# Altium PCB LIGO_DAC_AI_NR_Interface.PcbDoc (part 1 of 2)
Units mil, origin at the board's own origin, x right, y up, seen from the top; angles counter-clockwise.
Board outline 2600 x 10000 mil, 4 copper layers (Top Layer, Mid-Layer 1, Mid-Layer 2, Bottom Layer), stack 61.8 mil thick; 21 components, 77 nets, 221 pads, 42 vias.
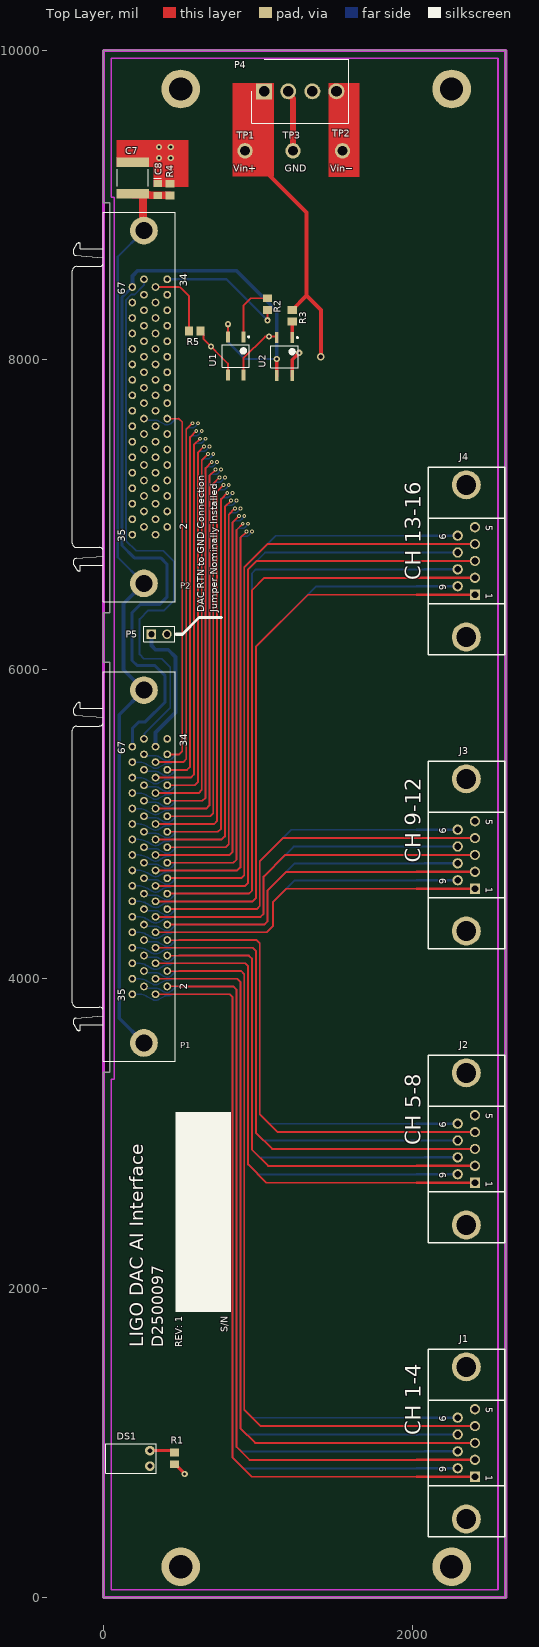
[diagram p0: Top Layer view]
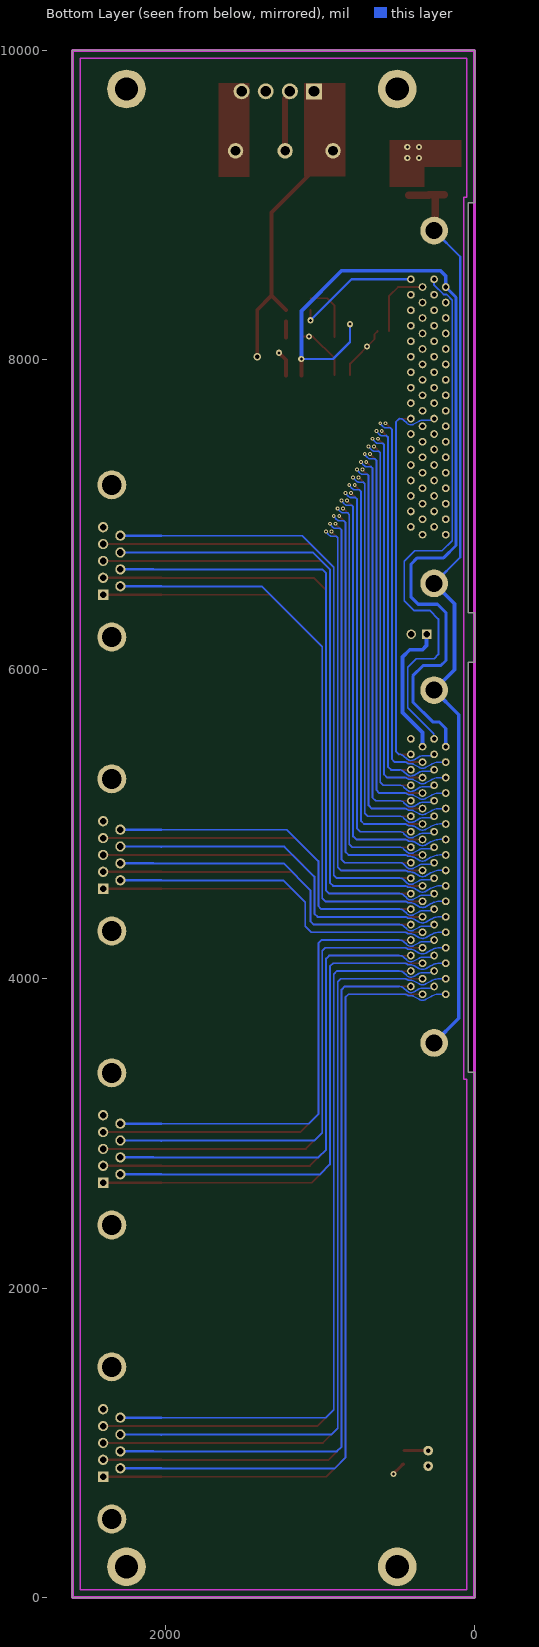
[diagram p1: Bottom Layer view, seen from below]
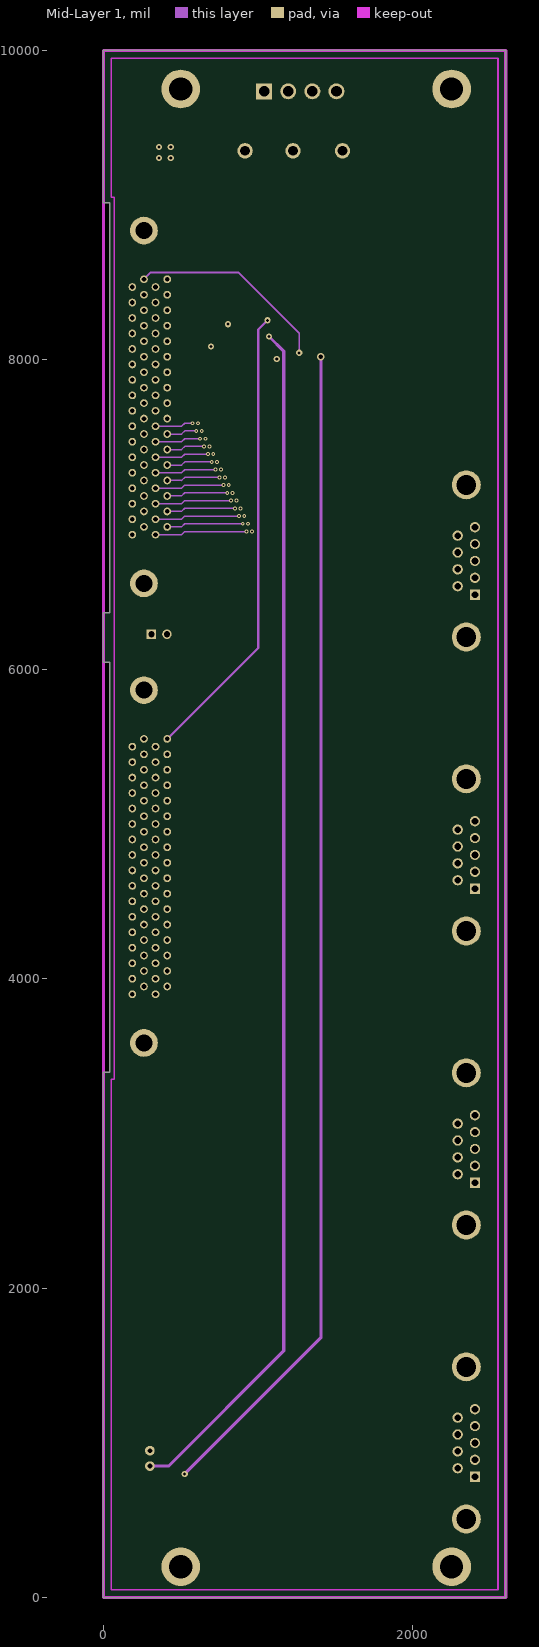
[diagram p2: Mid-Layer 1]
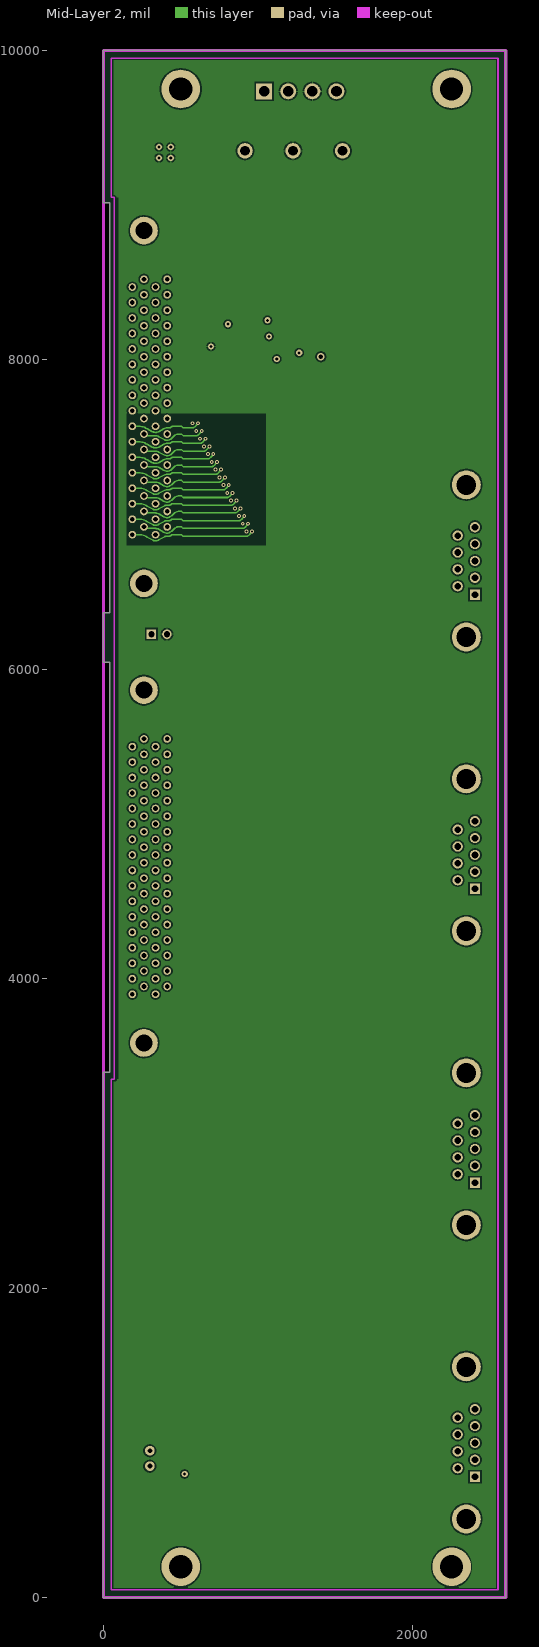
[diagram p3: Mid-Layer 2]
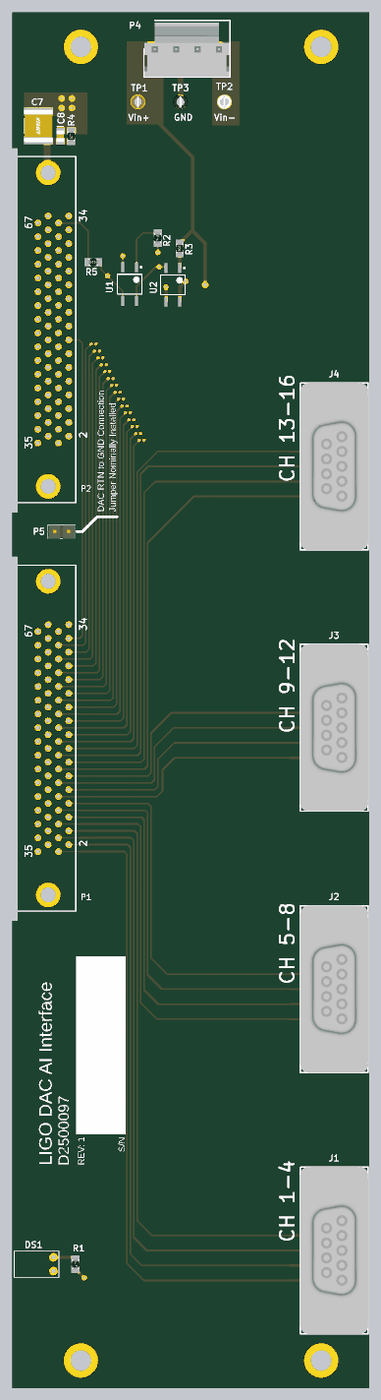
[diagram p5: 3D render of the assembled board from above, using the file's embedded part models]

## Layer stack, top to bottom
Top Solder: solder mask 0.4, Solder Resist, Dk 3.5
Top Layer: signal copper 1.4
Dielectric4: prepreg 8.6, FR-4, Dk 4.8
Mid-Layer 1: signal copper 1.4
Dielectric2: core 39, FR-4, Dk 4.8
Mid-Layer 2: signal copper 1.4
Dielectric3: prepreg 8.6, FR-4, Dk 4.8
Bottom Layer: signal copper 1.4
Bottom Solder: solder mask 0.4, Solder Resist, Dk 3.5

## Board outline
0,0 0,3395 40,3395 40,6045 0,6045 0,6365 40,6365 40,9015 0,9015 0,10000 2600,10000 2600,0

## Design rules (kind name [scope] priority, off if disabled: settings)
Clearance [All] p1: gap=10 ignorepadtopadclearanceinfootprint=FALSE
ComponentClearance ComponentClearance_1 [InComponent('P1')] p1: gap=0 collisioncheckmode=3 verticalgap=0 showdistances=FALSE
ComponentClearance ComponentClearance_2 [InComponent('P2')] p2: gap=0 collisioncheckmode=3 verticalgap=0 showdistances=FALSE
ComponentClearance ComponentClearance_3 [InComponent('DS1')] p3: gap=0 collisioncheckmode=3 verticalgap=0 showdistances=FALSE
ComponentClearance [All] p4: gap=10 collisioncheckmode=3 verticalgap=10 showdistances=FALSE
HoleSize [All] p1: absolutevalues=TRUE maxlimit=250 minlimit=12 maxpercent=80.000 minpercent=20.000
MinimumAnnularRing [All] p1: minimumring=6.5
PolygonConnect [All] p1: connectstyle=Relief reliefconductorwidth=10 reliefentries=4 polygonreliefangle="90 Angle" airgapwidth=10
RoutingVias [All] p1: holewidth=20 width=40 viastyle="Through Hole" minholewidth=12 minwidth=25 maxholewidth=28 maxwidth=50
SilkToSolderMaskClearance SilkscreenOverComponentPads [IsPad] p1: minsilkscreentomaskgap=5 clearancetoexposedcopper=TRUE
SolderMaskExpansion SolderMaskExpansion_1 [IsVia And (HoleDiameter = 12)] p1: expansion=5 istentingtop=FALSE
SolderMaskExpansion [All] p2: expansion=4 istentingtop=FALSE
SupplyNets "Schematic Supply Nets_4" [InNet('DGND')] p1: voltage=0.000
SupplyNets "Schematic Supply Nets_3" [InNet('Vin+')] p2: voltage=0.000
SupplyNets "Schematic Supply Nets_2" [InNet('GND')] p3: voltage=0.000
SupplyNets "Schematic Supply Nets_1" [InNet('Vin-')] p4: voltage=0.000
Width [All] p1: maxlimit=100 minlimit=8 preferedwidth=12
27 further rules are at their usual default settings.

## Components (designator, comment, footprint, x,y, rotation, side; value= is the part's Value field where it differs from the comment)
C7 "47u" CC5650-2220 190,9175 r270 top
C8 "100n" CC2013-0805 350,9100 r270 top
DS1 "LED" LED-1 300,900 r180 top
J1 "DB9F" DB9F-ST 2345,1000 r270 top locked
J2 "DB9F" DB9F-ST 2345,2900 r270 top locked
J3 "DB9F" DB9F-ST 2345,4800 r270 top
J4 "DB9F" DB9F-ST 2345,6700 r270 top locked
P1 "787082-7" 787082-7 0,4725 r90 top locked
P2 "787082-7" 787082-7 0,7695 r90 top locked
P4 "26-61-4040" HDRV4W155P0X396_1X4_1570X1001X1536P 1038.19,9735 r180 top
P5 "Header 2" TSW-102-XX-YY-S 310,6226.5 r0 top
R1 "2.21K" CR2012-0805 460,900 r270 top
R2 "499" CR2012-0805 1060,8360 r90 top
R3 "2.21K" CR2012-0805 1220,8285 r90 top
R4 "NL" CR2012-0805 430,9100 r90 top
R5 "NL" CR2012-0805 590,8185 r0 top
TP1 "Vin+" TP1-RED 915,9350 r0 top
TP2 "Vin−" TP1-WHT 1545,9350 r0 top
TP3 "GND" TP1-BLK 1225,9350 r0 top
U1 "PS2702-1-F3-A" PS2701A-1 855,8025 r270 top
U2 "PS2702-1-F3-A" PS2701A-1 1170,8020 r270 top

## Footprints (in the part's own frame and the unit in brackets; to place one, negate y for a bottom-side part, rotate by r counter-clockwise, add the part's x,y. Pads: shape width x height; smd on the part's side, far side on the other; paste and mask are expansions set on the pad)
787082-7 [mm] "Connector; D Subminiature 050 Series; 68 Position; Right Angle"
  round 1.27 hole 0.762: 1(-20.955,-8.555) 2(-19.685,-10.46) 3(-18.415,-8.555) 4(-17.145,-10.46) 5(-15.875,-8.555) 6(-14.605,-10.46) 7(-13.335,-8.555) 8(-12.065,-10.46) 9(-10.795,-8.555) 10(-9.525,-10.46) 11(-8.255,-8.555) 12(-6.985,-10.46) 13(-5.715,-8.555) 14(-4.445,-10.46) 15(-3.175,-8.555) 16(-1.905,-10.46) 17(-0.635,-8.555) 18(0.635,-10.46) 19(1.905,-8.555) 20(3.175,-10.46) 21(4.445,-8.555) 22(5.715,-10.46) 23(6.985,-8.555) 24(8.255,-10.46) 25(9.525,-8.555) 26(10.795,-10.46) 27(12.065,-8.555) 28(13.335,-10.46) 29(14.605,-8.555) 30(15.875,-10.46) 31(17.145,-8.555) 32(18.415,-10.46) 33(19.685,-8.555) 34(20.955,-10.46) 35(-20.955,-4.745) 36(-19.685,-6.65) 37(-18.415,-4.745) 38(-17.145,-6.65) 39(-15.875,-4.745) 40(-14.605,-6.65) 41(-13.335,-4.745) 42(-12.065,-6.65) 43(-10.795,-4.745) 44(-9.525,-6.65) 45(-8.255,-4.745) 46(-6.985,-6.65) 47(-5.715,-4.745) 48(-4.445,-6.65) 49(-3.175,-4.745) 50(-1.905,-6.65) 51(-0.635,-4.745) 52(0.635,-6.65) 53(1.905,-4.745) 54(3.175,-6.65) 55(4.445,-4.745) 56(5.715,-6.65) 57(6.985,-4.745) 58(8.255,-6.65) 59(9.525,-4.745) 60(10.795,-6.65) 61(12.065,-4.745) 62(13.335,-6.65) 63(14.605,-4.745) 64(15.875,-6.65) 65(17.145,-4.745) 66(18.415,-6.65) 67(19.685,-4.745) 68(20.955,-6.65)
  round 4.55 hole 2.77: 69(-28.955,-6.65) 70(28.955,-6.65)
  silkscreen extent -31.95,-11.76 31.95,5.11
CC2013-0805 [mm] "Chip Capacitor; Body 2.0 x 1.3 mm (LxW typ)"
  rect 1.15x1.4 smd: 1(-0.975,0) 2(0.975,0)
  silkscreen extent -1.85,-0.6 -1.85,0.6, body extent -1.1,-0.72 1.1,0.73, height 0.88
CC5650-2220 [mm] "Chip Capacitor, Body 5.6 x 5.0mm (LxW typ)"
  rect 1.6x5.3 smd: 1(-2.6,0) 2(2.6,0)
  silkscreen extent -1.4,-2.55 1.4,2.55, body extent -3.05,-2.7 3.05,2.7, height 1.8
CR2012-0805 [mm] "Chip Resistor; Body 2.0 x 1.3 mm (LxW typ)"
  rect 1.3x1.5 smd: 1(-0.95,0) 2(0.95,0)
  body extent -1,-0.62 1,0.63, height 0.46
DB9F-ST [mm] "Receptiacle; D Subminiature 9 Position; Straight"
  rect 1.69x1.69 hole 1.09: 1(5.54,1.42)
  round 1.69 hole 1.09: 2(2.77,1.42) 3(0,1.42) 4(-2.77,1.42) 5(-5.54,1.42) 6(4.155,-1.42) 7(1.385,-1.42) 8(-1.385,-1.42) 9(-4.155,-1.42)
  round 4.76 hole 3.26: 10(12.495,0) 11(-12.495,0)
  silkscreen extent -15.4,-6.27 15.4,6.27, body extent -15.44,-6.3 15.44,6.3, height 12.32
HDRV4W155P0X396_1X4_1570X1001X1536P [mm]
  rect 2.625x2.625 hole 1.75: 1(0,0)
  round 2.625 hole 1.75: 2(-3.96,0) 3(-7.92,0) 4(-11.88,0)
  silkscreen extent -13.91,-5.26 2.03,5.26, body extent -13.79,-4.83 1.91,5.17, height 14.73
LED-1 [mm] "Typical RED GaAs LED; 2 Leads"
  round 1.6 hole 0.8: 1(0,1.27) 2(0,-1.27)
  silkscreen extent -1.02,-2.41 7.24,2.41
PS2701A-1 [mm] "SOP, 4-Leads, Body 4.5x4.4mm (max), Pitch 2.54mm, IPC Medium Density"
  rect 1.8x0.6 smd: 1(-3.125,1.27) 2(-3.125,-1.27) 3(3.125,-1.27) 4(3.125,1.27)
  silkscreen extent -3.25,-2.25 1.83,2.25, body extent -2.2,-2.25 2.2,2.25, height 2.3
TP1-BLK [mm] "Testpoint pin, black"
  round 2.54 hole 1.58: 1(0,0)
  body extent -1.27,-1.27 1.27,1.27, height 4.89
TP1-RED [mm] "Testpoint pin, red"
  round 2.54 hole 1.58: 1(0,0)
  body extent -1.27,-1.27 1.27,1.27, height 4.89
TP1-WHT [mm] "Testpoint pin, white"
  round 2.54 hole 1.58: 1(0,0)
  body extent -1.27,-1.27 1.27,1.27, height 4.89
TSW-102-XX-YY-S [mm]
  rect 1.55x1.55 hole 1.02: 1(0,0)
  round 1.55 hole 1.02: 2(2.54,0)
  silkscreen extent -1.27,-1.27 3.81,1.27, body extent -1.39,-1.28 3.82,1.26, height 9.16

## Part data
C7: library part ChipCap, "Capacitor, surface mount", Part Number=445-C5750X7R1V476M230KCCT-ND, Tolerance=10%, Voltage Rating=35V
C8: library part ChipCap, "Capacitor, surface mount", Part Number=311-1140-1-ND, Tolerance=10%
DS1: "Panel mount LED", Part Number=67-1304-ND
J1 J2 J3 J4: "Receptacle Assembly, 9 Position, Right Angle, .318 Series", Part Number=A34072-ND
P1 P2: "Receptacle Assembly, Shielded, Right Angle, AMPLIMITE", Part Number=A31814-ND
P4: "Connector", Manufacturer_Name=Molex, Part Number=WM5226-ND
P5: "Header, 2-Pin", Part Number=SAM10844-ND
R1 R3: library part ChipRes1, "Resistor, surface mount", Part Number=311-2.21KCRCT-ND, Tolerance=1%
R2: library part ChipRes1, "Resistor, surface mount", Part Number=311-499CRCT-ND, Tolerance=1%
R4 R5: library part ChipRes1, "Resistor, surface mount", Tolerance=1%
TP1: library part TP_POSITIVE, "Testpoint, red", Part Number=5005K-ND
TP2: library part TP_NEGATIVE, "Testpoint, white", Part Number=5007K-ND
TP3: library part TP_GND, "Testpoint, black", Part Number=5006K-ND
U1 U2: library part PS2701A, "High Isolation Voltage SOP Photocoupler", Part Number=559-1027-1-ND

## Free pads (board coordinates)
  round 250 hole 150: 0(2250,200) 1(2250,9750) 2(500,9750) 3(500,200)

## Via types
v1: diameter 25, hole 12, Top Layer to Bottom Layer, 30 vias
v2: diameter 40, hole 20, Top Layer to Bottom Layer, 11 vias
v3: diameter 50, hole 28, Top Layer to Bottom Layer, 1 vias

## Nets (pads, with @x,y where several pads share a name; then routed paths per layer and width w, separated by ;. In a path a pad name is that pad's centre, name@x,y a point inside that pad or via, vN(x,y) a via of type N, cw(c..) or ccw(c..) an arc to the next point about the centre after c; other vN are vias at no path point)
DGND: P1.67 P2.67 U1.2 U2.3 | length 5753.1
  Top Layer w15: U1.2@805,8148.03 v2(805,8230)
  Top Layer w25: U2.3@1120,7896.97 v2(1120,8005)
  Bottom Layer w15: v2(805,8230) 805,8115 915,8005 v2(1120,8005)
  Bottom Layer w18: 120,6800 120,8403.19
  Bottom Layer w20: 120,6800 200,6720 370,6720 410,6680 410,6465 365,6420 240,6420 185,6365 185,6057 218,6024 332,6024 399,5957 399,5788 271,5660 230,5660 186.81,5616.81 P1.67@186.81,5500 ; 120,8403.19 P2.67@186.81,8470
  Bottom Layer w25: P2.67@186.81,8470 186.81,8541.81 220,8575 860,8575 1120,8315 v2(1120,8005)
GND: C7.1 C8.1 P4.2 P4.3 P5.2 R4.2 R5.2 TP3.1 U1.3 | length 745.2
  Top Layer w12: R5.2@627.4,8185 646.99,8165.41 646.99,8133.01 805,7975 U1.3@805,7901.97
  Top Layer w40: P4.2@1206,9725 1206,9705.95 1225,9686.95 TP3.1@1225,9350 TP3.1@1225,9344.27
  other v2: 695,8085 360,9305 435,9305 360,9375 435,9375
InputN1: J1.6 P1.35 | length 5137.8
  Bottom Layer w9: P1.35@186.81,3900 224.74,3900 226.94,3900 cw(c226.94,3794.19) 283.01,3883.92 283.21,3883.81 315.61,3866.08 ccw(c336.81,3900) 336.81,3860 ccw(c336.81,3900) 358.01,3866.08 390.61,3883.92 cw(c411.81,3850) 411.81,3890 424.74,3890 ccw(c424.74,3907.07) 436.81,3895 cw(c448.88,3882.93) 448.88,3900 486.81,3900
  Bottom Layer w12: 486.81,3900 815,3900 835,3880 835,905 905,835 2030,835
  Bottom Layer w15: 2025,835.89 2075,836.42 J1.6@2289.09,836.42
InputN2: J1.7 P1.36 | length 5025.8
  Bottom Layer w9: P1.36@261.81,3950 ccw(c285.95,3974.14) 285.95,3940 336.81,3940 cw(c336.81,3900) 358.01,3933.92 390.61,3916.08 ccw(c411.81,3950) 411.81,3910 ccw(c411.81,3950) 440.1,3921.72 440.1,3921.92 456.46,3938.28 cw(c484.74,3910) 484.74,3950 486.81,3950
  Bottom Layer w12: 486.81,3950 840,3950 860,3930 860,975 890.05,944.95 2025,944.95
  Bottom Layer w15: 2025,944.95 2075,945.47 J1.7@2289.09,945.47
InputN3: J1.8 P1.37 | length 5030.8
  Bottom Layer w9: P1.37@186.81,4000 224.74,4000 226.94,4000 cw(c226.94,3894.19) 283.01,3983.92 283.21,3983.81 315.61,3966.08 ccw(c336.81,4000) 336.81,3960 ccw(c336.81,4000) 358.01,3966.08 390.61,3983.92 cw(c411.81,3950) 411.81,3990 424.74,3990 ccw(c424.74,4007.07) 436.81,3995 cw(c448.88,3982.93) 448.88,4000 486.81,4000
  Bottom Layer w12: 486.81,4000 865,4000 885,3980 885,1095 926,1054 2025,1054
  Bottom Layer w15: 2025,1054 2075,1054.53 J1.8@2289.09,1054.53
InputN4: J1.9 P1.38 | length 4894.9
  Bottom Layer w9: P1.38@261.81,4050 ccw(c285.95,4074.14) 285.95,4040 336.81,4040 cw(c336.81,4000) 358.01,4033.92 390.61,4016.08 ccw(c411.81,4050) 411.81,4010 ccw(c411.81,4050) 440.1,4021.72 440.1,4021.92 456.46,4038.28 cw(c484.74,4010) 484.74,4050 486.81,4050
  Bottom Layer w12: 486.81,4050 890,4050 910,4030 910,1215 961.94,1163.06 2025,1163.06
  Bottom Layer w15: 2025,1163.06 2075,1163.58 J1.9@2289.09,1163.58
InputN5: J2.6 P1.39 | length 3435.4
  Bottom Layer w9: P1.39@186.81,4100 224.74,4100 226.94,4100 cw(c226.94,3994.19) 283.01,4083.92 283.21,4083.81 315.61,4066.08 ccw(c336.81,4100) 336.81,4060 ccw(c336.81,4100) 358.01,4066.08 390.61,4083.92 cw(c411.81,4050) 411.81,4090 424.74,4090 ccw(c424.74,4107.07) 436.81,4095 cw(c448.88,4082.93) 448.88,4100 486.81,4100
  Bottom Layer w12: 486.81,4100 915,4100 935,4080 935,2800 999.11,2735.89 2025,2735.89
  Bottom Layer w15: 2025,2735.89 2075,2736.42 J2.6@2289.09,2736.42
InputN6: J2.7 P1.40 | length 3314.1
  Bottom Layer w9: P1.40@261.81,4150 ccw(c285.95,4174.14) 285.95,4140 336.81,4140 cw(c336.81,4100) 358.01,4133.92 390.61,4116.08 ccw(c411.81,4150) 411.81,4110 ccw(c411.81,4150) 440.1,4121.72 440.1,4121.92 456.46,4138.28 cw(c484.74,4110) 484.74,4150 486.81,4150
  Bottom Layer w12: 486.81,4150 940,4150 960,4130 960,2895 1010.06,2844.95 2025,2844.95
  Bottom Layer w15: 2025,2844.95 2075,2845.47 J2.7@2289.09,2845.47
InputN7: J2.8 P1.41 | length 3324.9
  Bottom Layer w9: P1.41@186.81,4200 224.74,4200 226.94,4200 cw(c226.94,4094.19) 283.01,4183.92 283.21,4183.81 315.61,4166.08 ccw(c336.81,4200) 336.81,4160 ccw(c336.81,4200) 358.01,4166.08 390.61,4183.92 cw(c411.81,4150) 411.81,4190 424.74,4190 ccw(c424.74,4207.07) 436.81,4195 cw(c448.88,4182.93) 448.88,4200 486.81,4200
  Bottom Layer w12: 486.81,4200 965,4200 985,4180 985,3005 1036,2954 2025,2954
  Bottom Layer w15: 2025,2954 2075,2954.53 J2.8@2289.09,2954.53
InputN8: J2.9 P1.42 | length 3189
  Bottom Layer w9: P1.42@261.81,4250 ccw(c285.95,4274.14) 285.95,4240 336.81,4240 cw(c336.81,4200) 358.01,4233.92 390.61,4216.08 ccw(c411.81,4250) 411.81,4210 ccw(c411.81,4250) 440.1,4221.72 440.1,4221.92 456.46,4238.28 cw(c484.74,4210) 484.74,4250 486.81,4250
  Bottom Layer w12: 486.81,4250 990,4250 1010,4230 1010,3125 1071.94,3063.06 2025,3063.06
  Bottom Layer w15: 2025,3063.06 2075,3063.58 J2.9@2289.09,3063.58
InputN9: J3.6 P1.43 | length 2350.5
  Bottom Layer w9: P1.43@186.81,4300 224.74,4300 226.94,4300 cw(c226.94,4194.19) 283.01,4283.92 283.21,4283.81 315.61,4266.08 ccw(c336.81,4300) 336.81,4260 ccw(c336.81,4300) 358.01,4266.08 390.61,4283.92 cw(c411.81,4250) 411.81,4290 424.74,4290 ccw(c424.74,4307.07) 436.81,4295 cw(c448.88,4282.93) 448.88,4300 486.81,4300
  Bottom Layer w12: 486.81,4300 1055,4300 1095,4340 1095,4495 1235.89,4635.89 2025,4635.89
  Bottom Layer w15: 2025,4635.89 2075,4636.42 J3.6@2289.09,4636.42
InputN10: J3.7 P1.44 | length 2330.8
  Bottom Layer w9: P1.44@261.81,4350 ccw(c285.95,4374.14) 285.95,4340 336.81,4340 cw(c336.81,4300) 358.01,4333.92 390.61,4316.08 ccw(c411.81,4350) 411.81,4310 ccw(c411.81,4350) 440.1,4321.72 440.1,4321.92 456.46,4338.28 cw(c484.74,4310) 484.74,4350
  Bottom Layer w12: 484.74,4350 1040,4350 1060,4370 1060,4570 1234.95,4744.95 2025,4744.95
  Bottom Layer w15: 2025,4744.95 2075,4745.47 J3.7@2289.09,4745.47
InputN11: J3.8 P1.45 | length 2449.2
  Bottom Layer w9: P1.45@186.81,4400 224.74,4400 226.94,4400 cw(c226.94,4294.19) 283.01,4383.92 283.21,4383.81 315.61,4366.08 ccw(c336.81,4400) 336.81,4360 ccw(c336.81,4400) 358.01,4366.08 390.61,4383.92 cw(c411.81,4350) 411.81,4390 424.74,4390 ccw(c424.74,4407.07) 436.81,4395 cw(c448.88,4382.93) 448.88,4400
  Bottom Layer w12: 448.88,4400 1015,4400 1035,4420 1035,4660 1229,4854 2025,4854
  Bottom Layer w15: 2025,4854 2075,4854.53 J3.8@2289.09,4854.53
InputN12: J3.9 P1.46 | length 2432.4
  Bottom Layer w9: P1.46@261.81,4450 ccw(c285.95,4474.14) 285.95,4440 336.81,4440 cw(c336.81,4400) 358.01,4433.92 390.61,4416.08 ccw(c411.81,4450) 411.81,4410 ccw(c411.81,4450) 440.1,4421.72 440.1,4421.92 456.46,4438.28 cw(c484.74,4410) 484.74,4450
  Bottom Layer w12: 484.74,4450 990,4450 1010,4470 1010,4760 1213.06,4963.06 2025,4963.06
  Bottom Layer w15: 2025,4963.06 2075,4963.58 J3.9@2289.09,4963.58
InputN13: J4.6 P1.47 | length 3915.7
  Bottom Layer w9: P1.47@186.81,4500 224.74,4500 226.94,4500 cw(c226.94,4394.19) 283.01,4483.92 283.21,4483.81 315.61,4466.08 ccw(c336.81,4500) 336.81,4460 ccw(c336.81,4500) 358.01,4466.08 390.61,4483.92 cw(c411.81,4450) 411.81,4490 424.74,4490 ccw(c424.74,4507.07) 436.81,4495 cw(c448.88,4482.93) 448.88,4500
  Bottom Layer w12: 448.88,4500 965,4500 985,4520 985,6145 1375.89,6535.89 2025,6535.89
  Bottom Layer w15: 2025,6535.89 2075,6536.42 J4.6@2289.09,6536.42
InputN14: J4.7 P1.48 | length 4118.7
  Bottom Layer w9: P1.48@261.81,4550 ccw(c285.95,4574.14) 285.95,4540 336.81,4540 cw(c336.81,4500) 358.01,4533.92 390.61,4516.08 ccw(c411.81,4550) 411.81,4510 ccw(c411.81,4550) 440.1,4521.72 440.1,4521.92 456.46,4538.28 cw(c484.74,4510) 484.74,4550
  Bottom Layer w12: 484.74,4550 940,4550 960,4570 960,6620 984.94,6644.95 2025,6644.95
  Bottom Layer w15: 2025,6644.95 2075,6645.47 J4.7@2289.09,6645.47
InputN15: J4.8 P1.49 | length 4199
  Bottom Layer w9: P1.49@186.81,4600 224.74,4600 226.94,4600 cw(c226.94,4494.19) 283.01,4583.92 283.21,4583.81 315.61,4566.08 ccw(c336.81,4600) 336.81,4560 ccw(c336.81,4600) 358.01,4566.08 390.61,4583.92 cw(c411.81,4550) 411.81,4590 424.74,4590 ccw(c424.74,4607.07) 436.81,4595 cw(c448.88,4582.93) 448.88,4600
  Bottom Layer w12: 448.88,4600 915,4600 935,4620 935,6645 1044,6754 2025,6754
  Bottom Layer w15: 2025,6754 2075,6754.53 J4.8@2289.09,6754.53
InputN16: J4.9 P1.50 | length 4132.4
  Bottom Layer w9: P1.50@261.81,4650 ccw(c285.95,4674.14) 285.95,4640 336.81,4640 cw(c336.81,4600) 358.01,4633.92 390.61,4616.08 ccw(c411.81,4650) 411.81,4610 ccw(c411.81,4650) 440.1,4621.72 440.1,4621.92 456.46,4638.28 cw(c484.74,4610) 484.74,4650
  Bottom Layer w12: 484.74,4650 890,4650 910,4670 910,6660 1113.06,6863.06 2025,6863.06
  Bottom Layer w15: 2025,6863.06 2075,6863.58 J4.9@2289.09,6863.58
InputN17: P1.51 P2.35 | length 3757.4
  Mid-Layer 2 w8: v1@960,6887.52 v1(960,6890)
  Mid-Layer 2 w9: P2.35@186.81,6870 224.74,6870 226.94,6870 cw(c226.94,6764.19) 283.01,6853.92 283.21,6853.81 315.61,6836.08 ccw(c336.81,6870) 336.81,6830 ccw(c336.81,6870) 358.01,6836.08 390.61,6853.92 cw(c411.81,6820) 411.81,6860 424.74,6860 ccw(c424.74,6877.07) 436.81,6865 cw(c448.88,6852.93) 448.88,6870 486.81,6870 505,6870
  Mid-Layer 2 w10: 505,6870 515,6860 927.28,6860 ccw(c927.28,6870) 932.64,6861.55 935.28,6863.23 941.74,6868.19 ccw(c925,6890) 948.39,6875.54 cw(c956.89,6870.27) 949.79,6877.31 958.25,6885.77 ccw(c954.02,6890) v1(960,6890)
  Bottom Layer w8: v1@960,6887.52 v1(960,6890)
  Bottom Layer w9: P1.51@186.81,4700 224.74,4700 226.94,4700 cw(c226.94,4594.19) 283.01,4683.92 283.21,4683.81 315.61,4666.08 ccw(c336.81,4700) 336.81,4660 ccw(c336.81,4700) 358.01,4666.08 390.61,4683.92 cw(c411.81,4650) 411.81,4690 424.74,4690 ccw(c424.74,4707.07) 436.81,4695 cw(c448.88,4682.93) 448.88,4700
  Bottom Layer w10: 895,6860 927.28,6860 ccw(c927.28,6870) 932.64,6861.55 935.28,6863.23 941.74,6868.19 ccw(c925,6890) 948.39,6875.54 cw(c956.89,6870.27) 949.79,6877.31 958.25,6885.77 ccw(c954.02,6890) v1(960,6890)
  Bottom Layer w12: 448.88,4700 865,4700 885,4720 885,6846.81 ; 885,6850 895,6860
InputN18: P1.52 P2.36 | length 3566.4
  Mid-Layer 2 w8: v1@935,6937.52 v1(935,6940)
  Mid-Layer 2 w9: P2.36@261.81,6920 ccw(c285.95,6944.14) 285.95,6910 336.81,6910 cw(c336.81,6870) 358.01,6903.92 390.61,6886.08 ccw(c411.81,6920) 411.81,6880 ccw(c411.81,6920) 440.1,6891.72 440.1,6891.92 456.46,6908.28 cw(c484.74,6880) 484.74,6920 486.81,6920 505,6920
  Mid-Layer 2 w10: 505,6920 515,6910 902.28,6910 ccw(c902.28,6920) 907.64,6911.55 910.28,6913.23 916.74,6918.19 ccw(c900,6940) 923.39,6925.54 cw(c931.89,6920.27) 924.79,6927.31 933.25,6935.77 ccw(c929.02,6940) v1(935,6940)
  Bottom Layer w8: v1@935,6937.52 v1(935,6940)
  Bottom Layer w9: P1.52@261.81,4750 ccw(c285.95,4774.14) 285.95,4740 336.81,4740 cw(c336.81,4700) 358.01,4733.92 390.61,4716.08 ccw(c411.81,4750) 411.81,4710 ccw(c411.81,4750) 440.1,4721.72 440.1,4721.92 456.46,4738.28 cw(c484.74,4710) 484.74,4750
  Bottom Layer w10: 870,6910 902.28,6910 ccw(c902.28,6920) 907.64,6911.55 910.28,6913.23 916.74,6918.19 ccw(c900,6940) 923.39,6925.54 cw(c931.89,6920.27) 924.79,6927.31 933.25,6935.77 ccw(c929.02,6940) v1(935,6940)
  Bottom Layer w12: 484.74,4750 840,4750 860,4770 860,6896.81 ; 860,6900 870,6910
InputN19: P1.53 P2.37 | length 3657.4
  Mid-Layer 2 w8: v1@910,6987.52 v1(910,6990)
  Mid-Layer 2 w9: P2.37@186.81,6970 224.74,6970 226.94,6970 cw(c226.94,6864.19) 283.01,6953.92 283.21,6953.81 315.61,6936.08 ccw(c336.81,6970) 336.81,6930 ccw(c336.81,6970) 358.01,6936.08 390.61,6953.92 cw(c411.81,6920) 411.81,6960 424.74,6960 ccw(c424.74,6977.07) 436.81,6965 cw(c448.88,6952.93) 448.88,6970 486.81,6970 505,6970
  Mid-Layer 2 w10: 505,6970 515,6960 877.28,6960 ccw(c877.28,6970) 882.64,6961.55 885.28,6963.23 891.74,6968.19 ccw(c875,6990) 898.39,6975.54 cw(c906.89,6970.27) 899.79,6977.31 908.25,6985.77 ccw(c904.02,6990) v1(910,6990)
  Bottom Layer w8: v1@910,6987.52 v1(910,6990)
  Bottom Layer w9: P1.53@186.81,4800 224.74,4800 226.94,4800 cw(c226.94,4694.19) 283.01,4783.92 283.21,4783.81 315.61,4766.08 ccw(c336.81,4800) 336.81,4760 ccw(c336.81,4800) 358.01,4766.08 390.61,4783.92 cw(c411.81,4750) 411.81,4790 424.74,4790 ccw(c424.74,4807.07) 436.81,4795 cw(c448.88,4782.93) 448.88,4800
  Bottom Layer w10: 845,6960 877.28,6960 ccw(c877.28,6970) 882.64,6961.55 885.28,6963.23 891.74,6968.19 ccw(c875,6990) 898.39,6975.54 cw(c906.89,6970.27) 899.79,6977.31 908.25,6985.77 ccw(c904.02,6990) v1(910,6990)
  Bottom Layer w12: 448.88,4800 815,4800 835,4820 835,6946.81 ; 835,6950 845,6960
InputN20: P1.54 P2.38 | length 3466.4
  Mid-Layer 2 w8: v1@885,7037.52 v1(885,7040)
  Mid-Layer 2 w9: P2.38@261.81,7020 ccw(c285.95,7044.14) 285.95,7010 336.81,7010 cw(c336.81,6970) 358.01,7003.92 390.61,6986.08 ccw(c411.81,7020) 411.81,6980 ccw(c411.81,7020) 440.1,6991.72 440.1,6991.92 456.46,7008.28 cw(c484.74,6980) 484.74,7020 486.81,7020 505,7020
  Mid-Layer 2 w10: 505,7020 515,7010 852.28,7010 ccw(c852.28,7020) 857.64,7011.55 860.28,7013.23 866.74,7018.19 ccw(c850,7040) 873.39,7025.54 cw(c881.89,7020.27) 874.79,7027.31 883.25,7035.77 ccw(c879.02,7040) v1(885,7040)
  Bottom Layer w8: v1@885,7037.52 v1(885,7040)
  Bottom Layer w9: P1.54@261.81,4850 ccw(c285.95,4874.14) 285.95,4840 336.81,4840 cw(c336.81,4800) 358.01,4833.92 390.61,4816.08 ccw(c411.81,4850) 411.81,4810 ccw(c411.81,4850) 440.1,4821.72 440.1,4821.92 456.46,4838.28 cw(c484.74,4810) 484.74,4850
  Bottom Layer w10: 820,7010 852.28,7010 ccw(c852.28,7020) 857.64,7011.55 860.28,7013.23 866.74,7018.19 ccw(c850,7040) 873.39,7025.54 cw(c881.89,7020.27) 874.79,7027.31 883.25,7035.77 ccw(c879.02,7040) v1(885,7040)
  Bottom Layer w12: 484.74,4850 790,4850 810,4870 810,6996.81 ; 810,7000 820,7010
InputN21: P1.55 P2.39 | length 3557.4
  Mid-Layer 2 w8: v1@860,7087.52 v1(860,7090)
  Mid-Layer 2 w9: P2.39@186.81,7070 224.74,7070 226.94,7070 cw(c226.94,6964.19) 283.01,7053.92 283.21,7053.81 315.61,7036.08 ccw(c336.81,7070) 336.81,7030 ccw(c336.81,7070) 358.01,7036.08 390.61,7053.92 cw(c411.81,7020) 411.81,7060 424.74,7060 ccw(c424.74,7077.07) 436.81,7065 cw(c448.88,7052.93) 448.88,7070 486.81,7070 505,7070
  Mid-Layer 2 w10: 505,7070 515,7060 827.28,7060 ccw(c827.28,7070) 832.64,7061.55 835.28,7063.23 841.74,7068.19 ccw(c825,7090) 848.39,7075.54 cw(c856.89,7070.27) 849.79,7077.31 858.25,7085.77 ccw(c854.02,7090) v1(860,7090)
  Bottom Layer w8: v1@860,7087.52 v1(860,7090)
  Bottom Layer w9: P1.55@186.81,4900 224.74,4900 226.94,4900 cw(c226.94,4794.19) 283.01,4883.92 283.21,4883.81 315.61,4866.08 ccw(c336.81,4900) 336.81,4860 ccw(c336.81,4900) 358.01,4866.08 390.61,4883.92 cw(c411.81,4850) 411.81,4890 424.74,4890 ccw(c424.74,4907.07) 436.81,4895 cw(c448.88,4882.93) 448.88,4900
  Bottom Layer w10: 795,7060 827.28,7060 ccw(c827.28,7070) 832.64,7061.55 835.28,7063.23 841.74,7068.19 ccw(c825,7090) 848.39,7075.54 cw(c856.89,7070.27) 849.79,7077.31 858.25,7085.77 ccw(c854.02,7090) v1(860,7090)
  Bottom Layer w12: 448.88,4900 765,4900 785,4920 785,7046.81 ; 785,7050 795,7060
InputN22: P1.56 P2.40 | length 3366.4
  Mid-Layer 2 w8: v1@835,7137.52 v1(835,7140)
  Mid-Layer 2 w9: P2.40@261.81,7120 ccw(c285.95,7144.14) 285.95,7110 336.81,7110 cw(c336.81,7070) 358.01,7103.92 390.61,7086.08 ccw(c411.81,7120) 411.81,7080 ccw(c411.81,7120) 440.1,7091.72 440.1,7091.92 456.46,7108.28 cw(c484.74,7080) 484.74,7120 486.81,7120 505,7120
  Mid-Layer 2 w10: 505,7120 515,7110 802.28,7110 ccw(c802.28,7120) 807.64,7111.55 810.28,7113.23 816.74,7118.19 ccw(c800,7140) 823.39,7125.54 cw(c831.89,7120.27) 824.79,7127.31 833.25,7135.77 ccw(c829.02,7140) v1(835,7140)
  Bottom Layer w8: v1@835,7137.52 v1(835,7140)
  Bottom Layer w9: P1.56@261.81,4950 ccw(c285.95,4974.14) 285.95,4940 336.81,4940 cw(c336.81,4900) 358.01,4933.92 390.61,4916.08 ccw(c411.81,4950) 411.81,4910 ccw(c411.81,4950) 440.1,4921.72 440.1,4921.92 456.46,4938.28 cw(c484.74,4910) 484.74,4950
  Bottom Layer w10: 770,7110 802.28,7110 ccw(c802.28,7120) 807.64,7111.55 810.28,7113.23 816.74,7118.19 ccw(c800,7140) 823.39,7125.54 cw(c831.89,7120.27) 824.79,7127.31 833.25,7135.77 ccw(c829.02,7140) v1(835,7140)
  Bottom Layer w12: 484.74,4950 740,4950 760,4970 760,7096.81 ; 760,7100 770,7110
InputN23: P1.57 P2.41 | length 3457.4
  Mid-Layer 2 w8: v1@810,7187.52 v1(810,7190)
  Mid-Layer 2 w9: P2.41@186.81,7170 224.74,7170 226.94,7170 cw(c226.94,7064.19) 283.01,7153.92 283.21,7153.81 315.61,7136.08 ccw(c336.81,7170) 336.81,7130 ccw(c336.81,7170) 358.01,7136.08 390.61,7153.92 cw(c411.81,7120) 411.81,7160 424.74,7160 ccw(c424.74,7177.07) 436.81,7165 cw(c448.88,7152.93) 448.88,7170 486.81,7170 505,7170
  Mid-Layer 2 w10: 505,7170 515,7160 777.28,7160 ccw(c777.28,7170) 782.64,7161.55 785.28,7163.23 791.74,7168.19 ccw(c775,7190) 798.39,7175.54 cw(c806.89,7170.27) 799.79,7177.31 808.25,7185.77 ccw(c804.02,7190) v1(810,7190)
  Bottom Layer w8: v1@810,7187.52 v1(810,7190)
  Bottom Layer w9: P1.57@186.81,5000 224.74,5000 226.94,5000 cw(c226.94,4894.19) 283.01,4983.92 283.21,4983.81 315.61,4966.08 ccw(c336.81,5000) 336.81,4960 ccw(c336.81,5000) 358.01,4966.08 390.61,4983.92 cw(c411.81,4950) 411.81,4990 424.74,4990 ccw(c424.74,5007.07) 436.81,4995 cw(c448.88,4982.93) 448.88,5000
  Bottom Layer w10: 745,7160 777.28,7160 ccw(c777.28,7170) 782.64,7161.55 785.28,7163.23 791.74,7168.19 ccw(c775,7190) 798.39,7175.54 cw(c806.89,7170.27) 799.79,7177.31 808.25,7185.77 ccw(c804.02,7190) v1(810,7190)
  Bottom Layer w12: 448.88,5000 715,5000 735,5020 735,7146.81 ; 735,7150 745,7160
InputN24: P1.58 P2.42 | length 3266.4
  Mid-Layer 2 w8: v1@785,7237.52 v1(785,7240)
  Mid-Layer 2 w9: P2.42@261.81,7220 ccw(c285.95,7244.14) 285.95,7210 336.81,7210 cw(c336.81,7170) 358.01,7203.92 390.61,7186.08 ccw(c411.81,7220) 411.81,7180 ccw(c411.81,7220) 440.1,7191.72 440.1,7191.92 456.46,7208.28 cw(c484.74,7180) 484.74,7220 486.81,7220 505,7220
  Mid-Layer 2 w10: 505,7220 515,7210 752.28,7210 ccw(c752.28,7220) 757.64,7211.55 760.28,7213.23 766.74,7218.19 ccw(c750,7240) 773.39,7225.54 cw(c781.89,7220.27) 774.79,7227.31 783.25,7235.77 ccw(c779.02,7240) v1(785,7240)
  Bottom Layer w8: v1@785,7237.52 v1(785,7240)
  Bottom Layer w9: P1.58@261.81,5050 ccw(c285.95,5074.14) 285.95,5040 336.81,5040 cw(c336.81,5000) 358.01,5033.92 390.61,5016.08 ccw(c411.81,5050) 411.81,5010 ccw(c411.81,5050) 440.1,5021.72 440.1,5021.92 456.46,5038.28 cw(c484.74,5010) 484.74,5050
  Bottom Layer w10: 720,7210 752.28,7210 ccw(c752.28,7220) 757.64,7211.55 760.28,7213.23 766.74,7218.19 ccw(c750,7240) 773.39,7225.54 cw(c781.89,7220.27) 774.79,7227.31 783.25,7235.77 ccw(c779.02,7240) v1(785,7240)
  Bottom Layer w12: 484.74,5050 690,5050 710,5070 710,7196.81 ; 710,7200 720,7210
InputN25: P1.59 P2.43 | length 3357.4
  Mid-Layer 2 w8: v1@760,7287.52 v1(760,7290)
  Mid-Layer 2 w9: P2.43@186.81,7270 224.74,7270 226.94,7270 cw(c226.94,7164.19) 283.01,7253.92 283.21,7253.81 315.61,7236.08 ccw(c336.81,7270) 336.81,7230 ccw(c336.81,7270) 358.01,7236.08 390.61,7253.92 cw(c411.81,7220) 411.81,7260 424.74,7260 ccw(c424.74,7277.07) 436.81,7265 cw(c448.88,7252.93) 448.88,7270 486.81,7270 505,7270
  Mid-Layer 2 w10: 505,7270 515,7260 727.28,7260 ccw(c727.28,7270) 732.64,7261.55 735.28,7263.23 741.74,7268.19 ccw(c725,7290) 748.39,7275.54 cw(c756.89,7270.27) 749.79,7277.31 758.25,7285.77 ccw(c754.02,7290) v1(760,7290)
  Bottom Layer w8: v1@760,7287.52 v1(760,7290)
  Bottom Layer w9: P1.59@186.81,5100 224.74,5100 226.94,5100 cw(c226.94,4994.19) 283.01,5083.92 283.21,5083.81 315.61,5066.08 ccw(c336.81,5100) 336.81,5060 ccw(c336.81,5100) 358.01,5066.08 390.61,5083.92 cw(c411.81,5050) 411.81,5090 424.74,5090 ccw(c424.74,5107.07) 436.81,5095 cw(c448.88,5082.93) 448.88,5100
  Bottom Layer w10: 695,7260 727.28,7260 ccw(c727.28,7270) 732.64,7261.55 735.28,7263.23 741.74,7268.19 ccw(c725,7290) 748.39,7275.54 cw(c756.89,7270.27) 749.79,7277.31 758.25,7285.77 ccw(c754.02,7290) v1(760,7290)
  Bottom Layer w12: 448.88,5100 665,5100 685,5120 685,7246.81 ; 685,7250 695,7260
